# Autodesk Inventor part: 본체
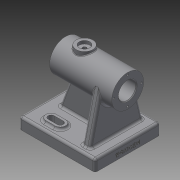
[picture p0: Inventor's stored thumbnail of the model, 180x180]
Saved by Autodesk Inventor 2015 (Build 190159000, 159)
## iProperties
Created: 2022-06
Part Number: 본체
Material: 일반
Document SubType Name: Modeling
Designer: 104-1
Density: 1 g/cm^3
Appearance: 기본값
Author: 104-1
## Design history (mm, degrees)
sketch "스케치1"
  geometry: L1 (-50, 43)-(50, 43); L2 (50, 43)-(50, -43); L3 (50, -43)-(-50, -43); L4 (-50, -43)-(-50, 43); L5 (-50, 43)-(50, -43); L6 (50, 43)-(-50, -43); 1 further point
  constraints: 12 end point, 2 midpoint, 2 parallel, 1 horizontal, 1 perpendicular
  dimensions: "d0" = 100 distance of L1.start L1.end; "d1" = 86 distance of L3.end L1.start
extrude "돌출1" new body sketch "스케치1" distance "d2" = 15; taper "d3" = 0 deg
node "작업 평면1"
sketch "스케치4"
  geometry: L1 (-15, 86)-(0, 86) reference; L2 (0, 86)-(0, 0) reference; L3 (0, 0)-(-15, 0) reference; L4 (-15, 0)-(-15, 86) reference; L5 (-76.814, 22.559)-(-15, 8); L6 (-76.814, 63.441)-(-15, 78); L7 (-15, 86)-(-15, 0) reference; L8 (-76.814, 22.559)-(-76.814, 63.441); L9 (-15, 78)-(-15, 8); A1 r 21 centre (-72, 43) between (-76.814, 22.559) and (-76.814, 63.441); 1 further point
  constraints: 8 end point, 2 point on circle, 2 point on line, 2 tangent, 1 centre point, 1 collinear, 1 vertical
  dimensions: "d17" = 42 diameter of A1; "d18" = 72 distance of point (0, 43) A1.centre; "d19" = 8 distance from line of L6.end L1; "d20" = 8 distance of L3.end L5.end
extrude "돌출4" join sketch "스케치4" distance "d21" = 10; taper "d22" = 0 deg
sketch "스케치5"
  geometry: L1 (35, 35)-(35, -35) reference; L2 (-50, 43)-(-50, -43) reference; L3 (-35, 5)-(35, 5); L4 (35, 5)-(35, -5); L5 (35, -5)-(-35, -5); L6 (-35, -5)-(-35, 5); 2 further points
  constraints: 8 end point, 2 midpoint, 2 parallel, 1 horizontal, 1 perpendicular
  dimensions: "d23" = 10 distance of L5.end L3.start; "d24" = 15 distance between parallel lines of L6 L2
extrude "돌출5" join sketch "스케치5" distance "d25" = 57; taper "d26" = 0 deg
feature "면 기울기2" dims angle "d30" = 20 deg
sketch "스케치9"
  geometry: L1 (50, 43)-(-50, 43) reference; L2 (-50, 43)-(-50, -43) reference; L3 (-24, 27)-(-12, 27); L4 (-24, 20)-(-12, 20); L5 (-12, 34)-(-24, 34); A1 r 7 centre (-24, 27) between (-24, 34) and (-24, 20); A2 r 7 centre (-12, 27) between (-12, 20) and (-12, 34); 2 further points
  constraints: 8 end point, 4 point on circle, 4 tangent, 2 centre point, 1 horizontal, 1 midpoint, 1 parallel
  dimensions: "d53" = 12 distance of L3.end L3.start; "d54" = 26 distance from line of L2 L3.start; "d55" = 16 distance from line of L3.start L1; "d56" = 27 vertical distance of point (0, 0) L3.start (derived); "d58" = 14 distance between parallel lines of L4 L5
extrude "돌출7" join sketch "스케치9" distance "d59" = 3; taper "d60" = 0 deg
sketch "스케치10"
  geometry: L1 (-12, 27)-(-24, 27); L2 (-12, 23)-(-24, 23); L3 (-24, 31)-(-12, 31); L4 (-24, 34)-(-12, 34) reference; L5 (-12, 20)-(-24, 20) reference; L6 (-33.908, -5)-(-33.908, 5) reference; L7 (-33.908, 5)-(25, 5) reference; L8 (25, 5)-(25, 34.293) reference; L9 (25, 34.293)-(35, 34.293) reference; L10 (35, 34.293)-(35, -34.293) reference; L11 (35, -34.293)-(25, -34.293) reference; L12 (25, -34.293)-(25, -5) reference; L13 (25, -5)-(-33.908, -5) reference; L14 (50, 43)-(-50, 43) reference; L15 (-50, 43)-(-50, -43) reference; A1 r 7 centre (-24, 27) between (-24, 34) and (-24, 20) reference; A2 r 4 centre (-12, 27) between (-12, 23) and (-12, 31); A3 r 4 centre (-24, 27) between (-24, 31) and (-24, 23); A4 r 7 centre (-24, 27) between (-24, 34) and (-24, 20) reference; A5 r 7 centre (-12, 27) between (-12, 20) and (-12, 34) reference; 2 further points
  constraints: 8 end point, 4 point on circle, 4 tangent, 2 centre point, 1 horizontal, 1 midpoint, 1 parallel
  dimensions: "d61" = 8 distance between parallel lines of L3 L2; "d63" = 16 distance from line of L14 L1.end; "d64" = 26 distance from line of L1.end L15; "d65" = 12 distance of L1.start A1.centre
extrude "돌출8" cut sketch "스케치10" stored distance "d66" = 3; taper "d67" = 0 deg
fillet "모깎기1" dims "d68" = 3
sketch "스케치14"
  geometry: L1 (0, 86)-(0, 0) reference; C1 r 21 at (-72, 43); 2 further points
  constraints: 1 centre point, 1 horizontal alignment, 1 midpoint
  dimensions: "d77" = 72 distance from line of L1 C1.centre; "d78" = 42 diameter of C1
extrude "돌출11" join sketch "스케치14" distance "d79" = 82; taper "d80" = 0 deg
node "작업 평면5"
sketch "스케치15"
  geometry: L1 (50, 43)-(50, -43) reference; L2 (32, -21)-(32, 21) reference; C1 r 11 at (7, 0); 1 further point
  constraints: 1 centre point, 1 horizontal alignment
  dimensions: "d82" = 22 diameter of C1; "d84" = 25 distance from line of L2 C1.centre
extrude "돌출12" join sketch "스케치15" stored distance "d85" = 20; taper "d86" = 0 deg
sketch "스케치16"
  geometry: C1 r 21 at (0, 0) reference; 2 further points
  constraints: 1 horizontal alignment
  dimensions: "d87" = 18 distance of point (-18, 0) C1.centre
hole "구멍3" sketch "스케치16" at (-18, 0) diameter "d88" = 2.459; stored, may be unused: countersink angle "d92" = 90 deg, drill point angle "d94" = 118 deg; dims "d89" = 8, "d90" = 4, "d91" = 2, "d93" = 10
sketch "스케치17"
  geometry: C1 r 21 at (0, 0) reference; 2 further points
  constraints: 1 horizontal alignment
  dimensions: "d98" = 18 distance of point (18, 0) C1.centre
hole "구멍4" sketch "스케치17" at (18, 0) diameter "d99" = 2.459; stored, may be unused: countersink angle "d103" = 90 deg, drill point angle "d105" = 118 deg; dims "d100" = 8, "d101" = 4, "d102" = 2, "d104" = 10
sketch "스케치18"
  geometry: C1 r 11 at (0, 0) reference; C2 r 7 at (0, 0); 1 further point
  constraints: 1 centre point, 1 coincident
  dimensions: "d109" = 14 diameter of C2
extrude "돌출13" cut sketch "스케치18" distance "d110" = 4; taper "d111" = 0 deg
sketch "스케치19"
  geometry: L1 (-8.944, -6.403)-(-25, -6.403) reference; L2 (-25, -6.403)-(-25, 6.403) reference; L3 (-25, 6.403)-(-8.944, 6.403) reference; L4 (8.944, 6.403)-(57, 6.403) reference; L5 (57, 6.403)-(57, -6.403) reference; L6 (57, -6.403)-(8.944, -6.403) reference; A1 r 11 centre (0, 0) between (-8.944, -6.403) and (8.944, -6.403) reference; A2 r 11 centre (0, 0) between (8.944, 6.403) and (-8.944, 6.403) reference; 3 further points
  constraints: 2 horizontal alignment
hole "구멍5" sketch "스케치19" at (0, 0) diameter "d112" = 4.917; stored, may be unused: countersink angle "d116" = 90 deg, drill point angle "d118" = 118 deg; dims "d113" = 12, "d114" = 4, "d115" = 2, "d117" = 21
sketch "스케치20"
  geometry: C1 r 21 at (0, 0) reference; C2 r 11.5 at (0, 0); 1 further point
  constraints: 1 centre point, 1 coincident
  dimensions: "d119" = 23 diameter of C2
extrude "돌출14" cut sketch "스케치20" distance "d120" = 20; taper "d121" = 0 deg
sketch "스케치21"
  geometry: C1 r 21 at (0, 0) reference; C2 r 14.5 at (0, 0); 1 further point
  constraints: 1 centre point, 1 coincident
  dimensions: "d122" = 29 diameter of C2
extrude "돌출15" cut sketch "스케치21" distance "d123" = 62; taper "d124" = 0 deg
fillet "모깎기2" dims "d125" = 1
chamfer "모따기1" distance "d126" = 1; stored, may be unused: second distance "d127" = 2, angle "d128" = 45 deg
sketch "스케치22"
  geometry: L1 (0, 86)-(0, 0) reference; 3 further points
  constraints: 1 horizontal alignment, 1 midpoint, 1 other
  dimensions: "d129" = 6 distance from line of L1 point (-6, 43)
feature "엠보싱1" sketch "스케치22" dims "d0" = 100, "d1" = 86, "d130" = 0.5, "d131" = 0
fillet "모깎기3" dims "d132" = 3
fillet "모깎기4" dims "d133" = 3
fillet "모깎기5" dims "d134" = 3
fillet "모깎기6" dims "d135" = 3
node "솔리드1"
mirror "대칭1"
pattern_circular "원형 패턴3" dims angle "d96" = 360 deg
pattern_circular "원형 패턴4" dims angle "d107" = 360 deg
node "절단 모서리 투영1"
node "절단 모서리 투영2"
node "절단 모서리 투영4"
other parameters: "d16" = -15, "d81" = -96
